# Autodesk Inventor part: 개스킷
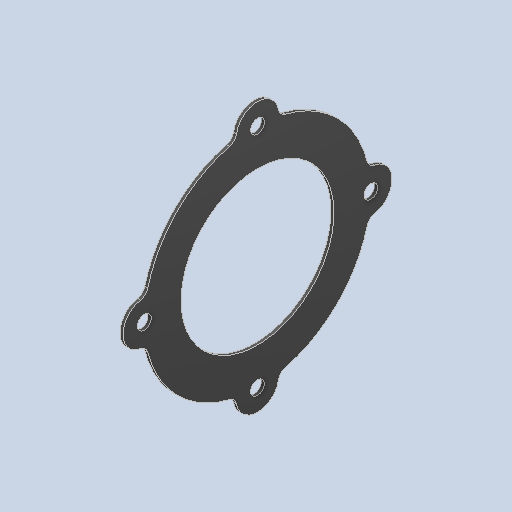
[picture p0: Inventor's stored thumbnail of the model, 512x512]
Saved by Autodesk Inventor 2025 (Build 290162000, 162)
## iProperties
Created: 2025-08
Part Number: 개스킷
Material: 황동, 연질 노란색
Document SubType Name: Modeling
Designer: infra04
Density: 8.47 g/cm^3
Appearance: 기본값
Author: jhkim
Sending System: Autodesk Inventor 2026
Preprocessor: ST-DEVELOPER v20.1
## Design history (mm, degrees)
feature "솔리드2"
node "솔리드1"
